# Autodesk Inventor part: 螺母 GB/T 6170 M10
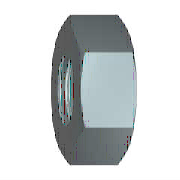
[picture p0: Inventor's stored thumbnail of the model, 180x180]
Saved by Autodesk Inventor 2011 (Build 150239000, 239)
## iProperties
Created: 2010-02
Part Number: 螺母 GB/T 6170 M10
Material: 低炭钢
Description: 1 型六角螺母
Document SubType Name: Modeling
Standard: GB/T 6170-2000
Designer: user
Standard Revision: 2000
Standards Organization: GB
Language: zh-CN
Size Designation: M10
Categories: <MemberInstance><Categories><Category DisplayName="紧固件" InternalName="e4da775c-781d-43d5-af7c-5136215cf5a6" Mnemonic="FSTN"><Category DisplayName="螺母" InternalN
Density: 1 g/cm^3
IsCustomPart: 1
Author: user
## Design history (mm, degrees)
body "Solid1"
sketch "Sketch1"
  geometry: L1 (-9.238, 0)-(-4.619, 8); L2 (-4.619, 8)-(4.619, 8); L3 (4.619, 8)-(9.238, 0); L4 (9.238, 0)-(4.619, -8); L5 (4.619, -8)-(-4.619, -8); L6 (-4.619, -8)-(-9.238, 0); 2 further points
  constraints: 12 end point, 1 coincident, 1 horizontal, 11 other
  dimensions: "d0" = 18.47521 distance of L3.end L1.start (= 1.1547 x SW)
workaxis "Work Axis1"
workplane "Work Plane1"
extrude "Body" new body sketch "Sketch1" distance "d1" = 8.4 (= KOH); taper "d2" = 0 deg
sketch "Sketch2"
  geometry: L1 (0, 4.619)-(0, 9.238) reference; L2 (0, 9.238)-(8.4, 9.238) reference; L3 (8.4, 4.619)-(8.4, 9.238) reference; L4 (-1.68, 0)-(10.08, 0) reference; L5 (0.715, 9.238)-(0, 8); L6 (7.685, 9.238)-(8.4, 8)
  constraints: 4 end point, 4 point on line
  dimensions: "d3" = 30 deg angle of L1 L5 (= ANG1); "d4" = 30 deg angle of L3 L6 (= ANG2); "d5" = 16 diameter of L5.end L4 (= SW0); "d6" = 16 diameter of L6.end L4 (= SW01)
revolve "Chamfer1" stored, may be unused: angle "d7" = 90 deg
sketch "Sketch3"
  geometry: A1 r 8 centre (0, 0) between (-4, -6.928) and (4, -6.928) reference; 1 further point
  constraints: 1 coincident
hole "Thread" sketch "Sketch3" diameter "d25" = 8.376; stored, may be unused: countersink angle "d29" = 82 deg, drill point angle "d31" = 118 deg; dims "d26" = 6, "d27" = 4, "d28" = 2, "d30" = 8
chamfer "Chamfer2" distance "d8" = 0.8119 (= -0.5 x GD1 + 0.5 x NND); stored, may be unused: angle "d9" = 30 deg, second distance "d40" = 0.8119 (= -0.5 x GD1 + 0.5 x NND)
chamfer "Chamfer3" distance "d10" = 0.8119 (= -0.5 x GD1 + 0.5 x NND); stored, may be unused: angle "d11" = 30 deg, second distance "d41" = 0.8119 (= -0.5 x GD1 + 0.5 x NND)
other parameters: "ANG1" = 30 deg [user parameter; used in 1 equation term], "ANG2" = 30 deg [user parameter; used in 1 equation term], "KOH" = 8.4 [user parameter; used in 1 equation term], "SW" = 16 [user parameter; used in 4 equation terms], "SW0" = 16 (= SW) [user parameter; used in 1 equation term], "SW01" = 16 (= SW) [user parameter; used in 1 equation term], "GD1" = 8.3762 (computed from THREADDIA, PTC, TOA) [user parameter; used in 4 equation terms], "d13" = 0, "d14" = 0, "d39" = 0, "d42" = 0, "GUL" = 0.8119 (= 0.541266 x PTC) [user parameter], "TPU" = 6.66667 (computed from PTC) [user parameter], "TOA" = 30 deg [user parameter; used in 1 equation term], "PTC" = 1.5 [user parameter; used in 4 equation terms], "E0" = 18.48 (= 1.155 x SW) [user parameter], "GAL" = 0.8119 (= 0.541266 x PTC) [user parameter]
